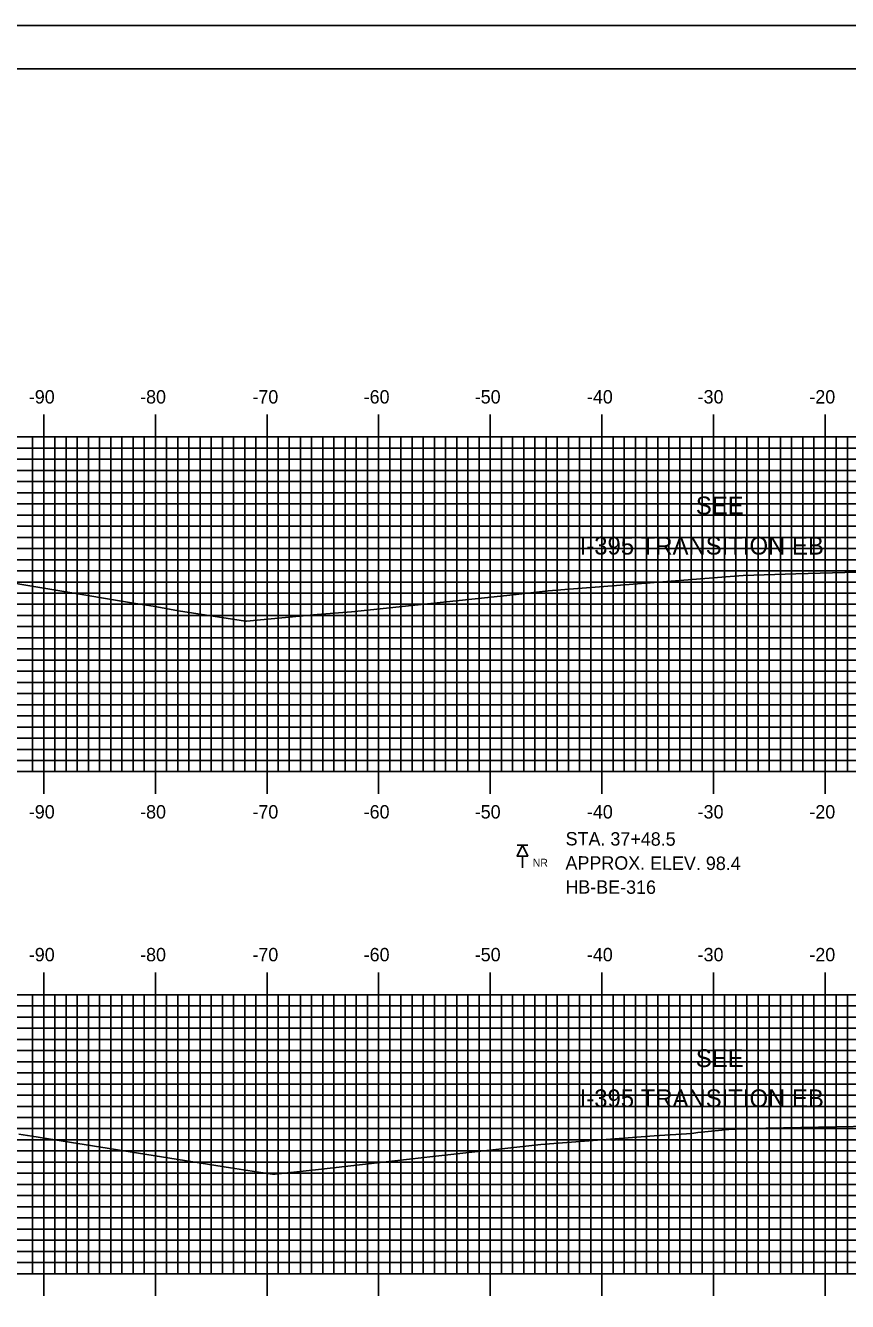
# Model space of a CAD drawing. Extents: x 843356 to 843699, y 363538 to 363758.
# Drawn here: x 843429.8 to 843503.4, y 363643.2 to 363757.6 of the extents above; entities that cross this region are included whole.
import ezdxf

# ---------------------------------------------------------------- set-up
doc = ezdxf.new("R2010")
doc.units = 0
for name, color, linetype in [('ANNOTATION', 7, 'Continuous'), ('BORDER', 7, 'Continuous'), ('BORING - NO REFUSAL', 7, 'Continuous'), ('H_V ANNOTATION', 7, 'Continuous'), ('MAJOR', 7, 'Continuous'), ('MINOR', 7, 'Continuous'), ('PLOT BOUNDARY', 7, 'Continuous'), ('S_Roadway_Centerline', 7, 'Continuous')]:
    doc.layers.add(name, color=color, linetype=linetype)

msp = doc.modelspace()

# ---------------------------------------------------------------- linework, layer by layer
at = {"layer": 'BORDER'}
msp.add_lwpolyline([(843371.82, 363543.72), (843691.82, 363543.72), (843691.82, 363753.72), (843371.82, 363753.72)], close=True, dxfattribs=at)
at = {"layer": 'BORING - NO REFUSAL'}
for p, q in [((843474.78, 363684.12), (843473.82, 363684.12)), ((843474.3, 363683.16), (843474.3, 363682.1))]:
    msp.add_line(p, q, dxfattribs=at)
msp.add_lwpolyline([(843474.3, 363684.12), (843474.78, 363683.16), (843473.82, 363683.16)], close=True, dxfattribs=at)
at = {"layer": 'MAJOR'}
for p, q in [((843431.42, 363722.73), (843431.42, 363720.72)), ((843441.42, 363722.73), (843441.42, 363720.72)), ((843451.42, 363722.73), (843451.42, 363720.72)), ((843461.42, 363722.73), (843461.42, 363720.72)), ((843471.42, 363722.73), (843471.42, 363720.72)), ((843481.42, 363722.73), (843481.42, 363720.72)), ((843491.42, 363722.73), (843491.42, 363720.72)), ((843501.42, 363722.73), (843501.42, 363720.72)), ((843381.42, 363720.72), (843661.42, 363720.72)), ((843381.42, 363720.72), (843661.42, 363720.72)), ((843431.42, 363690.72), (843431.42, 363720.72)), ((843441.42, 363690.72), (843441.42, 363720.72)), ((843451.42, 363690.72), (843451.42, 363720.72)), ((843461.42, 363690.72), (843461.42, 363720.72)), ((843471.42, 363690.72), (843471.42, 363720.72)), ((843481.42, 363690.72), (843481.42, 363720.72)), ((843491.42, 363690.72), (843491.42, 363720.72)), ((843501.42, 363690.72), (843501.42, 363720.72)), ((843381.42, 363715.72), (843661.42, 363715.72)), ((843381.42, 363710.72), (843661.42, 363710.72)), ((843381.42, 363705.72), (843661.42, 363705.72)), ((843381.42, 363700.72), (843661.42, 363700.72)), ((843381.42, 363695.72), (843661.42, 363695.72)), ((843381.42, 363690.72), (843661.42, 363690.72)), ((843381.42, 363690.72), (843661.42, 363690.72)), ((843431.42, 363688.72), (843431.42, 363690.72)), ((843441.42, 363688.72), (843441.42, 363690.72)), ((843451.42, 363688.72), (843451.42, 363690.72)), ((843461.42, 363688.72), (843461.42, 363690.72)), ((843471.42, 363688.72), (843471.42, 363690.72)), ((843481.42, 363688.72), (843481.42, 363690.72)), ((843491.42, 363688.72), (843491.42, 363690.72)), ((843501.42, 363688.72), (843501.42, 363690.72)), ((843431.42, 363672.73), (843431.42, 363670.72)), ((843441.42, 363672.73), (843441.42, 363670.72)), ((843451.42, 363672.73), (843451.42, 363670.72)), ((843461.42, 363672.73), (843461.42, 363670.72)), ((843471.42, 363672.73), (843471.42, 363670.72)), ((843481.42, 363672.73), (843481.42, 363670.72)), ((843491.42, 363672.73), (843491.42, 363670.72)), ((843501.42, 363672.73), (843501.42, 363670.72)), ((843381.42, 363670.72), (843661.42, 363670.72)), ((843381.42, 363670.72), (843661.42, 363670.72)), ((843431.42, 363645.72), (843431.42, 363670.72)), ((843441.42, 363645.72), (843441.42, 363670.72)), ((843451.42, 363645.72), (843451.42, 363670.72)), ((843461.42, 363645.72), (843461.42, 363670.72)), ((843471.42, 363645.72), (843471.42, 363670.72)), ((843481.42, 363645.72), (843481.42, 363670.72)), ((843491.42, 363645.72), (843491.42, 363670.72)), ((843501.42, 363645.72), (843501.42, 363670.72)), ((843381.42, 363665.72), (843661.42, 363665.72)), ((843381.42, 363660.72), (843661.42, 363660.72)), ((843381.42, 363655.72), (843661.42, 363655.72)), ((843381.42, 363650.72), (843661.42, 363650.72)), ((843381.42, 363645.72), (843661.42, 363645.72)), ((843381.42, 363645.72), (843661.42, 363645.72)), ((843431.42, 363643.72), (843431.42, 363645.72)), ((843441.42, 363643.72), (843441.42, 363645.72)), ((843451.42, 363643.72), (843451.42, 363645.72)), ((843461.42, 363643.72), (843461.42, 363645.72)), ((843471.42, 363643.72), (843471.42, 363645.72)), ((843481.42, 363643.72), (843481.42, 363645.72)), ((843491.42, 363643.72), (843491.42, 363645.72)), ((843501.42, 363643.72), (843501.42, 363645.72))]:
    msp.add_line(p, q, dxfattribs=at)
at = {"layer": 'MINOR'}
for p, q in [((843430.42, 363690.72), (843430.42, 363720.72)), ((843432.42, 363690.72), (843432.42, 363720.72)), ((843433.42, 363690.72), (843433.42, 363720.72)), ((843434.42, 363690.72), (843434.42, 363720.72)), ((843435.42, 363690.72), (843435.42, 363720.72)), ((843436.42, 363690.72), (843436.42, 363720.72)), ((843437.42, 363690.72), (843437.42, 363720.72)), ((843438.42, 363690.72), (843438.42, 363720.72)), ((843439.42, 363690.72), (843439.42, 363720.72)), ((843440.42, 363690.72), (843440.42, 363720.72)), ((843442.42, 363690.72), (843442.42, 363720.72)), ((843443.42, 363690.72), (843443.42, 363720.72)), ((843444.42, 363690.72), (843444.42, 363720.72)), ((843445.42, 363690.72), (843445.42, 363720.72)), ((843446.42, 363690.72), (843446.42, 363720.72)), ((843447.42, 363690.72), (843447.42, 363720.72)), ((843448.42, 363690.72), (843448.42, 363720.72)), ((843449.42, 363690.72), (843449.42, 363720.72)), ((843450.42, 363690.72), (843450.42, 363720.72)), ((843452.42, 363690.72), (843452.42, 363720.72)), ((843453.42, 363690.72), (843453.42, 363720.72)), ((843454.42, 363690.72), (843454.42, 363720.72)), ((843455.42, 363690.72), (843455.42, 363720.72)), ((843456.42, 363690.72), (843456.42, 363720.72)), ((843457.42, 363690.72), (843457.42, 363720.72)), ((843458.42, 363690.72), (843458.42, 363720.72)), ((843459.42, 363690.72), (843459.42, 363720.72)), ((843460.42, 363690.72), (843460.42, 363720.72)), ((843462.42, 363690.72), (843462.42, 363720.72)), ((843463.42, 363690.72), (843463.42, 363720.72)), ((843464.42, 363690.72), (843464.42, 363720.72)), ((843465.42, 363690.72), (843465.42, 363720.72)), ((843466.42, 363690.72), (843466.42, 363720.72)), ((843467.42, 363690.72), (843467.42, 363720.72)), ((843468.42, 363690.72), (843468.42, 363720.72)), ((843469.42, 363690.72), (843469.42, 363720.72)), ((843470.42, 363690.72), (843470.42, 363720.72)), ((843472.42, 363690.72), (843472.42, 363720.72)), ((843473.42, 363690.72), (843473.42, 363720.72)), ((843474.42, 363690.72), (843474.42, 363720.72)), ((843475.42, 363690.72), (843475.42, 363720.72)), ((843476.42, 363690.72), (843476.42, 363720.72)), ((843477.42, 363690.72), (843477.42, 363720.72)), ((843478.42, 363690.72), (843478.42, 363720.72)), ((843479.42, 363690.72), (843479.42, 363720.72)), ((843480.42, 363690.72), (843480.42, 363720.72)), ((843482.42, 363690.72), (843482.42, 363720.72)), ((843483.42, 363690.72), (843483.42, 363720.72)), ((843484.42, 363690.72), (843484.42, 363720.72)), ((843485.42, 363690.72), (843485.42, 363720.72)), ((843486.42, 363690.72), (843486.42, 363720.72)), ((843487.42, 363690.72), (843487.42, 363720.72)), ((843488.42, 363690.72), (843488.42, 363720.72)), ((843489.42, 363690.72), (843489.42, 363720.72)), ((843490.42, 363690.72), (843490.42, 363720.72)), ((843492.42, 363690.72), (843492.42, 363720.72)), ((843493.42, 363690.72), (843493.42, 363720.72)), ((843494.42, 363690.72), (843494.42, 363720.72)), ((843495.42, 363690.72), (843495.42, 363720.72)), ((843496.42, 363690.72), (843496.42, 363720.72)), ((843497.42, 363690.72), (843497.42, 363720.72)), ((843498.42, 363690.72), (843498.42, 363720.72)), ((843499.42, 363690.72), (843499.42, 363720.72)), ((843500.42, 363690.72), (843500.42, 363720.72)), ((843502.42, 363690.72), (843502.42, 363720.72)), ((843503.42, 363690.72), (843503.42, 363720.72)), ((843381.42, 363719.72), (843661.42, 363719.72)), ((843381.42, 363718.72), (843661.42, 363718.72)), ((843381.42, 363717.72), (843661.42, 363717.72)), ((843381.42, 363716.72), (843661.42, 363716.72)), ((843381.42, 363714.72), (843661.42, 363714.72)), ((843381.42, 363713.72), (843661.42, 363713.72)), ((843381.42, 363712.72), (843661.42, 363712.72)), ((843381.42, 363711.72), (843661.42, 363711.72)), ((843381.42, 363709.72), (843661.42, 363709.72)), ((843381.42, 363708.72), (843661.42, 363708.72)), ((843381.42, 363707.72), (843661.42, 363707.72)), ((843381.42, 363706.72), (843661.42, 363706.72)), ((843381.42, 363704.72), (843661.42, 363704.72)), ((843381.42, 363703.72), (843661.42, 363703.72)), ((843381.42, 363702.72), (843661.42, 363702.72)), ((843381.42, 363701.72), (843661.42, 363701.72)), ((843381.42, 363699.72), (843661.42, 363699.72)), ((843381.42, 363698.72), (843661.42, 363698.72)), ((843381.42, 363697.72), (843661.42, 363697.72)), ((843381.42, 363696.72), (843661.42, 363696.72)), ((843381.42, 363694.72), (843661.42, 363694.72)), ((843381.42, 363693.72), (843661.42, 363693.72)), ((843381.42, 363692.72), (843661.42, 363692.72)), ((843381.42, 363691.72), (843661.42, 363691.72)), ((843430.42, 363645.72), (843430.42, 363670.72)), ((843432.42, 363645.72), (843432.42, 363670.72)), ((843433.42, 363645.72), (843433.42, 363670.72)), ((843434.42, 363645.72), (843434.42, 363670.72)), ((843435.42, 363645.72), (843435.42, 363670.72)), ((843436.42, 363645.72), (843436.42, 363670.72)), ((843437.42, 363645.72), (843437.42, 363670.72)), ((843438.42, 363645.72), (843438.42, 363670.72)), ((843439.42, 363645.72), (843439.42, 363670.72)), ((843440.42, 363645.72), (843440.42, 363670.72)), ((843442.42, 363645.72), (843442.42, 363670.72)), ((843443.42, 363645.72), (843443.42, 363670.72)), ((843444.42, 363645.72), (843444.42, 363670.72)), ((843445.42, 363645.72), (843445.42, 363670.72)), ((843446.42, 363645.72), (843446.42, 363670.72)), ((843447.42, 363645.72), (843447.42, 363670.72)), ((843448.42, 363645.72), (843448.42, 363670.72)), ((843449.42, 363645.72), (843449.42, 363670.72)), ((843450.42, 363645.72), (843450.42, 363670.72)), ((843452.42, 363645.72), (843452.42, 363670.72)), ((843453.42, 363645.72), (843453.42, 363670.72)), ((843454.42, 363645.72), (843454.42, 363670.72)), ((843455.42, 363645.72), (843455.42, 363670.72)), ((843456.42, 363645.72), (843456.42, 363670.72)), ((843457.42, 363645.72), (843457.42, 363670.72)), ((843458.42, 363645.72), (843458.42, 363670.72)), ((843459.42, 363645.72), (843459.42, 363670.72)), ((843460.42, 363645.72), (843460.42, 363670.72)), ((843462.42, 363645.72), (843462.42, 363670.72)), ((843463.42, 363645.72), (843463.42, 363670.72)), ((843464.42, 363645.72), (843464.42, 363670.72)), ((843465.42, 363645.72), (843465.42, 363670.72)), ((843466.42, 363645.72), (843466.42, 363670.72)), ((843467.42, 363645.72), (843467.42, 363670.72)), ((843468.42, 363645.72), (843468.42, 363670.72)), ((843469.42, 363645.72), (843469.42, 363670.72)), ((843470.42, 363645.72), (843470.42, 363670.72)), ((843472.42, 363645.72), (843472.42, 363670.72)), ((843473.42, 363645.72), (843473.42, 363670.72)), ((843474.42, 363645.72), (843474.42, 363670.72)), ((843475.42, 363645.72), (843475.42, 363670.72)), ((843476.42, 363645.72), (843476.42, 363670.72)), ((843477.42, 363645.72), (843477.42, 363670.72)), ((843478.42, 363645.72), (843478.42, 363670.72)), ((843479.42, 363645.72), (843479.42, 363670.72)), ((843480.42, 363645.72), (843480.42, 363670.72)), ((843482.42, 363645.72), (843482.42, 363670.72)), ((843483.42, 363645.72), (843483.42, 363670.72)), ((843484.42, 363645.72), (843484.42, 363670.72)), ((843485.42, 363645.72), (843485.42, 363670.72)), ((843486.42, 363645.72), (843486.42, 363670.72)), ((843487.42, 363645.72), (843487.42, 363670.72)), ((843488.42, 363645.72), (843488.42, 363670.72)), ((843489.42, 363645.72), (843489.42, 363670.72)), ((843490.42, 363645.72), (843490.42, 363670.72)), ((843492.42, 363645.72), (843492.42, 363670.72)), ((843493.42, 363645.72), (843493.42, 363670.72)), ((843494.42, 363645.72), (843494.42, 363670.72)), ((843495.42, 363645.72), (843495.42, 363670.72)), ((843496.42, 363645.72), (843496.42, 363670.72)), ((843497.42, 363645.72), (843497.42, 363670.72)), ((843498.42, 363645.72), (843498.42, 363670.72)), ((843499.42, 363645.72), (843499.42, 363670.72)), ((843500.42, 363645.72), (843500.42, 363670.72)), ((843502.42, 363645.72), (843502.42, 363670.72)), ((843503.42, 363645.72), (843503.42, 363670.72)), ((843381.42, 363669.72), (843661.42, 363669.72)), ((843381.42, 363668.72), (843661.42, 363668.72)), ((843381.42, 363667.72), (843661.42, 363667.72)), ((843381.42, 363666.72), (843661.42, 363666.72)), ((843381.42, 363664.72), (843661.42, 363664.72)), ((843381.42, 363663.72), (843661.42, 363663.72)), ((843381.42, 363662.72), (843661.42, 363662.72)), ((843381.42, 363661.72), (843661.42, 363661.72)), ((843381.42, 363659.72), (843661.42, 363659.72)), ((843381.42, 363658.72), (843661.42, 363658.72)), ((843381.42, 363657.72), (843661.42, 363657.72)), ((843381.42, 363656.72), (843661.42, 363656.72)), ((843381.42, 363654.72), (843661.42, 363654.72)), ((843381.42, 363653.72), (843661.42, 363653.72)), ((843381.42, 363652.72), (843661.42, 363652.72)), ((843381.42, 363651.72), (843661.42, 363651.72)), ((843381.42, 363649.72), (843661.42, 363649.72)), ((843381.42, 363648.72), (843661.42, 363648.72)), ((843381.42, 363647.72), (843661.42, 363647.72)), ((843381.42, 363646.72), (843661.42, 363646.72))]:
    msp.add_line(p, q, dxfattribs=at)
at = {"layer": 'PLOT BOUNDARY'}
msp.add_lwpolyline([(843355.64, 363537.6), (843695.64, 363537.6), (843695.64, 363757.6), (843355.64, 363757.6)], close=True, dxfattribs=at)
at = {"layer": 'S_Roadway_Centerline'}
for points in [[(843425.68, 363708.12), (843439.63, 363705.78), (843441.23, 363705.55), (843443.48, 363705.15), (843449.48, 363704.22), (843449.57, 363704.2), (843455.92, 363704.8), (843458.99, 363705.05), (843473.47, 363706.58), (843476.62, 363706.92), (843478.49, 363707.09), (843481.22, 363707.29), (843492.91, 363708.2), (843494.09, 363708.31), (843498.8, 363708.44), (843502.08, 363708.53), (843509.73, 363708.75)], [(843429.19, 363658.24), (843430.36, 363658.06), (843448.14, 363655.22), (843450.86, 363654.78), (843451.9, 363654.64), (843452.15, 363654.64), (843456.02, 363655.07), (843464.19, 363655.99), (843466.27, 363656.22), (843475.96, 363657.29), (843486.12, 363658.07), (843489.49, 363658.3), (843490.02, 363658.37), (843493.1, 363658.66), (843493.45, 363658.68), (843496.11, 363658.76), (843505.52, 363658.93)]]:
    msp.add_lwpolyline(points, dxfattribs=at)

# ---------------------------------------------------------------- texts
at = {"layer": 'ANNOTATION'}
for s, p in [('SEE', (843489.84, 363713.78)), ('I-395 TRANSITION EB', (843479.43, 363710.18)), ('SEE', (843489.84, 363664.24)), ('I-395 TRANSITION EB', (843479.43, 363660.64))]:
    msp.add_text(s, height=1.6, dxfattribs=at).set_placement(p)
at = {"layer": 'BORING - NO REFUSAL'}
for s, p in [('STA. 37+48.5', (843478.17, 363684.11)), ('APPROX. ELEV. 98.4', (843478.16, 363681.95)), ('HB-BE-316', (843478.15, 363679.79))]:
    msp.add_text(s, height=1.2, rotation=359.8142, dxfattribs=at).set_placement(p)
msp.add_text('NR', height=0.7, dxfattribs=at).set_placement((843475.23, 363682.21))
at = {"layer": 'H_V ANNOTATION'}
for s, p in [('-90', (843430.08, 363723.72)), ('-80', (843440.05, 363723.72)), ('-70', (843450.11, 363723.72)), ('-60', (843460.08, 363723.72)), ('-50', (843470.03, 363723.72)), ('-40', (843480.08, 363723.72)), ('-30', (843490, 363723.72)), ('-20', (843500.01, 363723.72)), ('-90', (843430.08, 363686.52)), ('-80', (843440.05, 363686.52)), ('-70', (843450.11, 363686.52)), ('-60', (843460.08, 363686.52)), ('-50', (843470.03, 363686.52)), ('-40', (843480.08, 363686.52)), ('-30', (843490, 363686.52)), ('-20', (843500.01, 363686.52)), ('-90', (843430.08, 363673.72)), ('-80', (843440.05, 363673.72)), ('-70', (843450.11, 363673.72)), ('-60', (843460.08, 363673.72)), ('-50', (843470.03, 363673.72)), ('-40', (843480.08, 363673.72)), ('-30', (843490, 363673.72)), ('-20', (843500.01, 363673.72))]:
    msp.add_text(s, height=1.2, dxfattribs=at).set_placement(p)

doc.saveas('drawing.dxf')
